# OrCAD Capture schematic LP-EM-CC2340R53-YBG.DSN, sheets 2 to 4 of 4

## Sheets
2 2_Peripherals: size A3
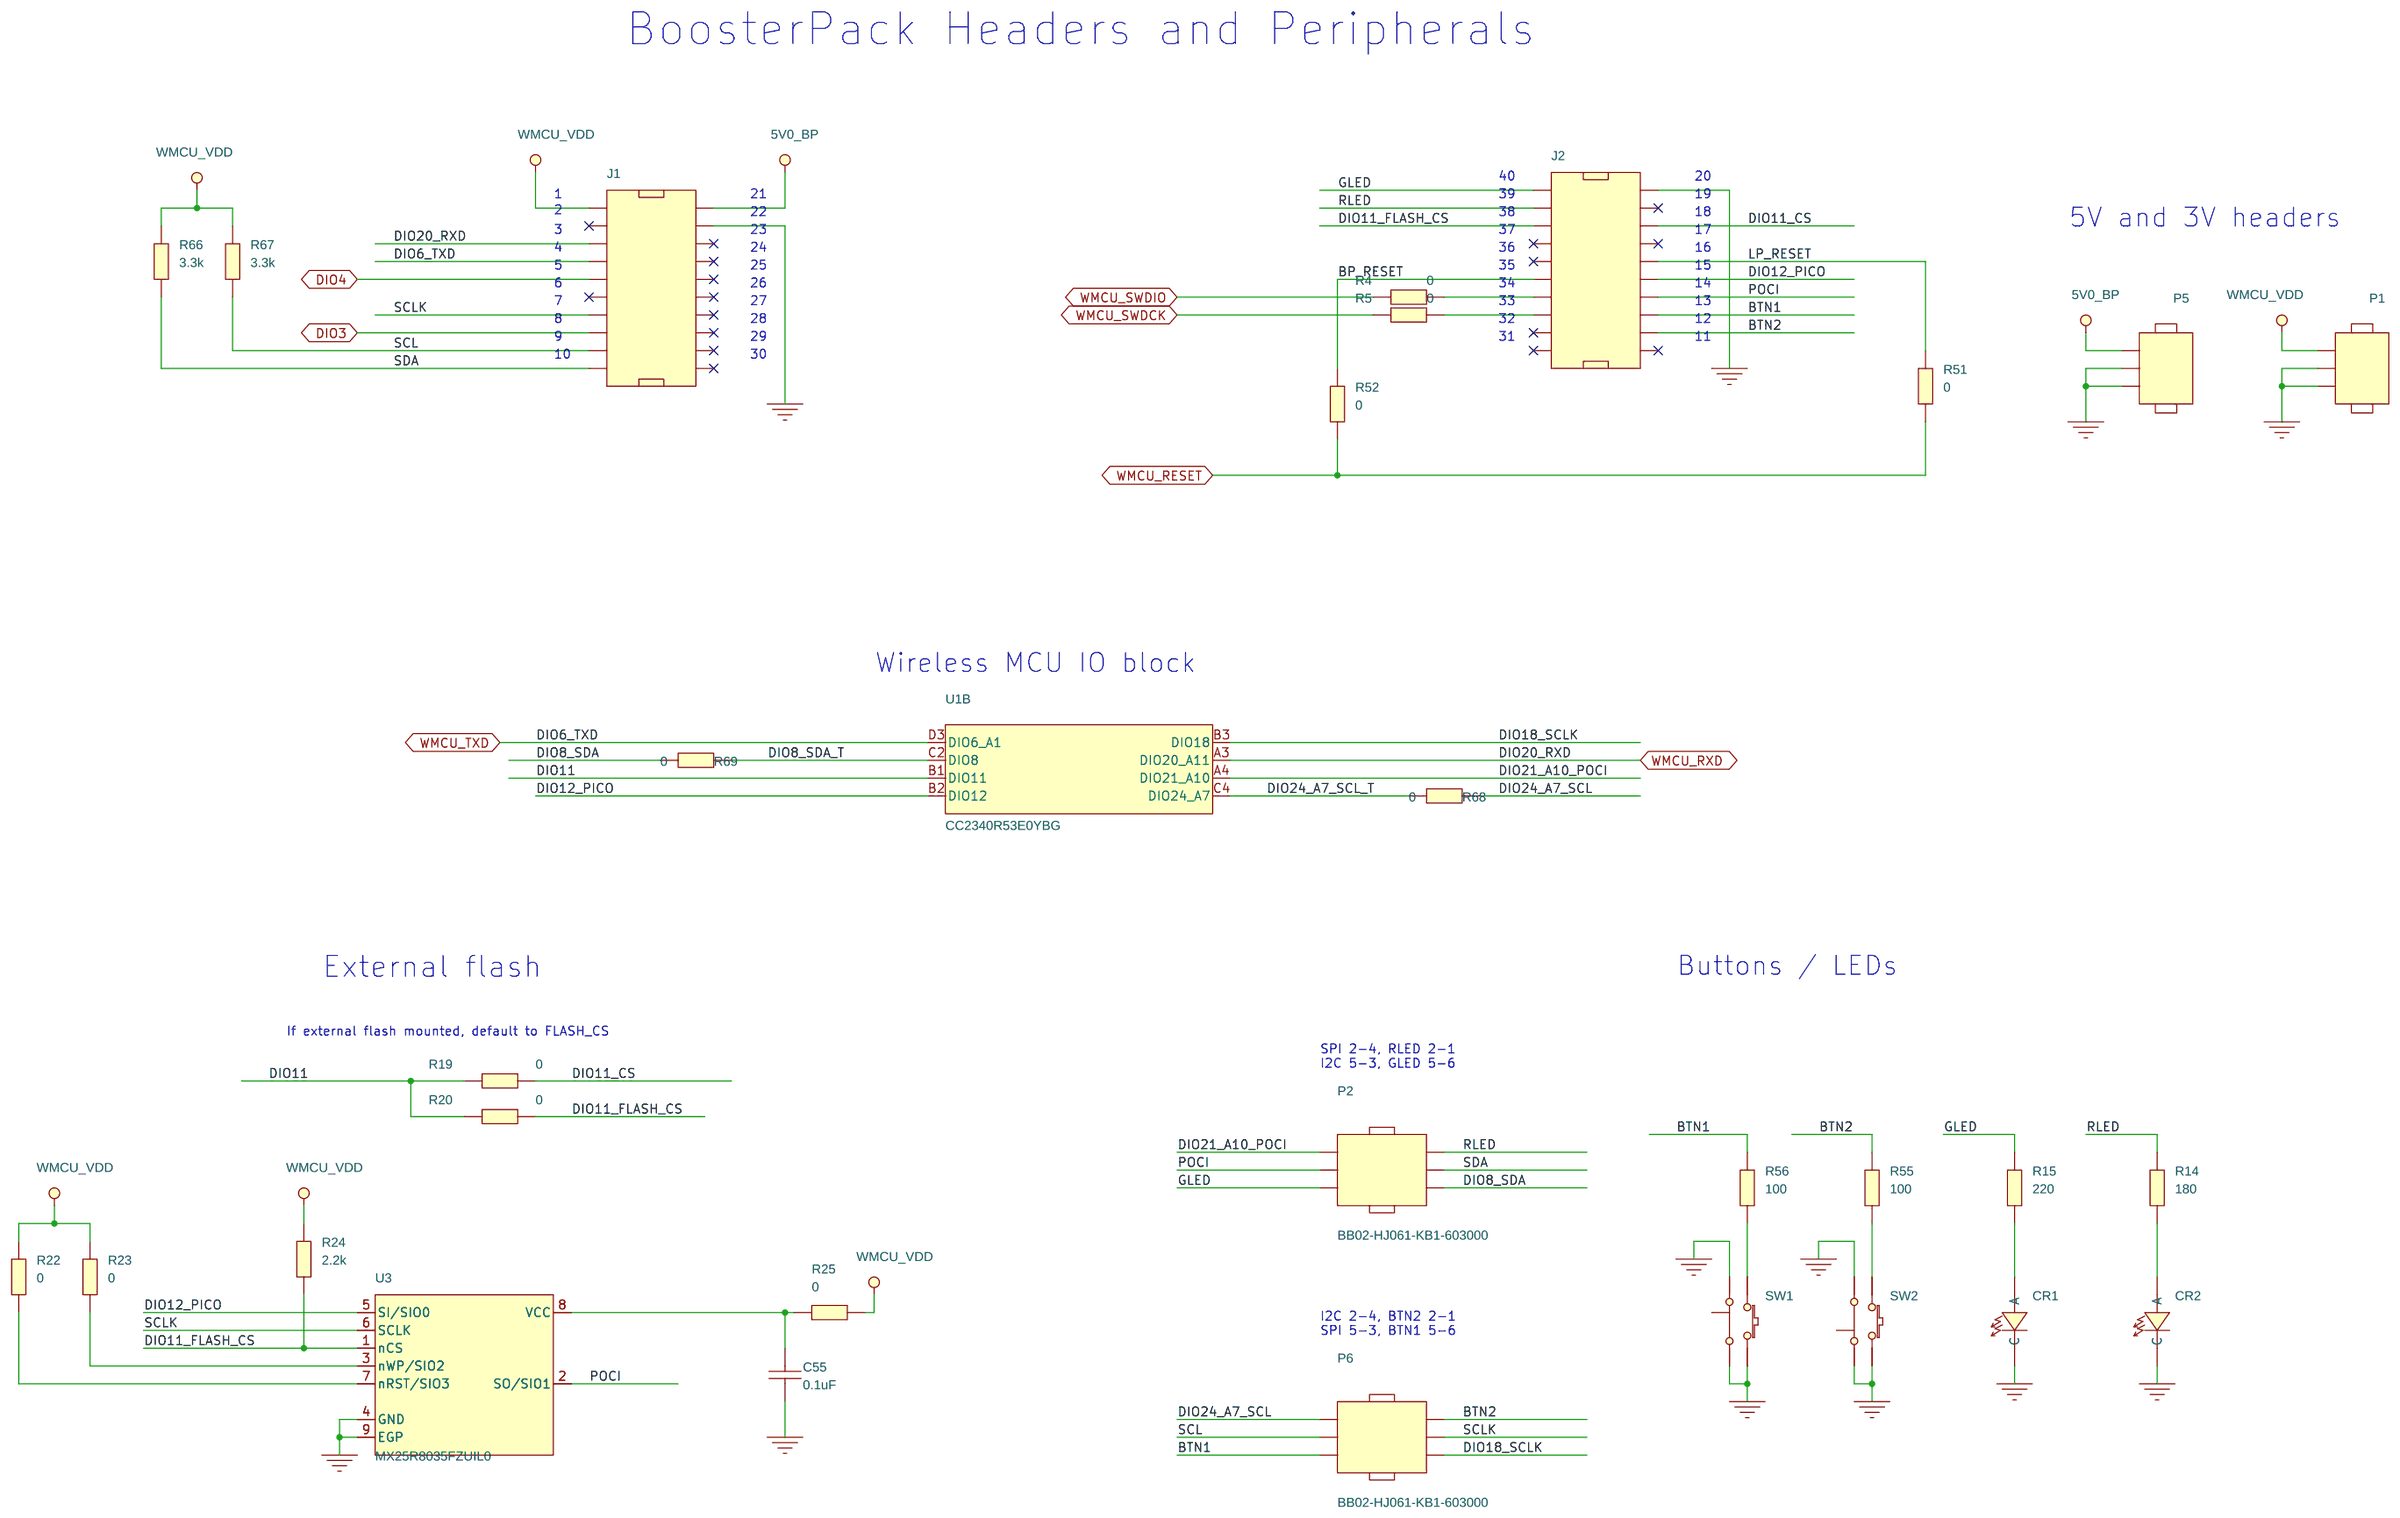
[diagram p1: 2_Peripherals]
3 3_Debugger Interface: size A3
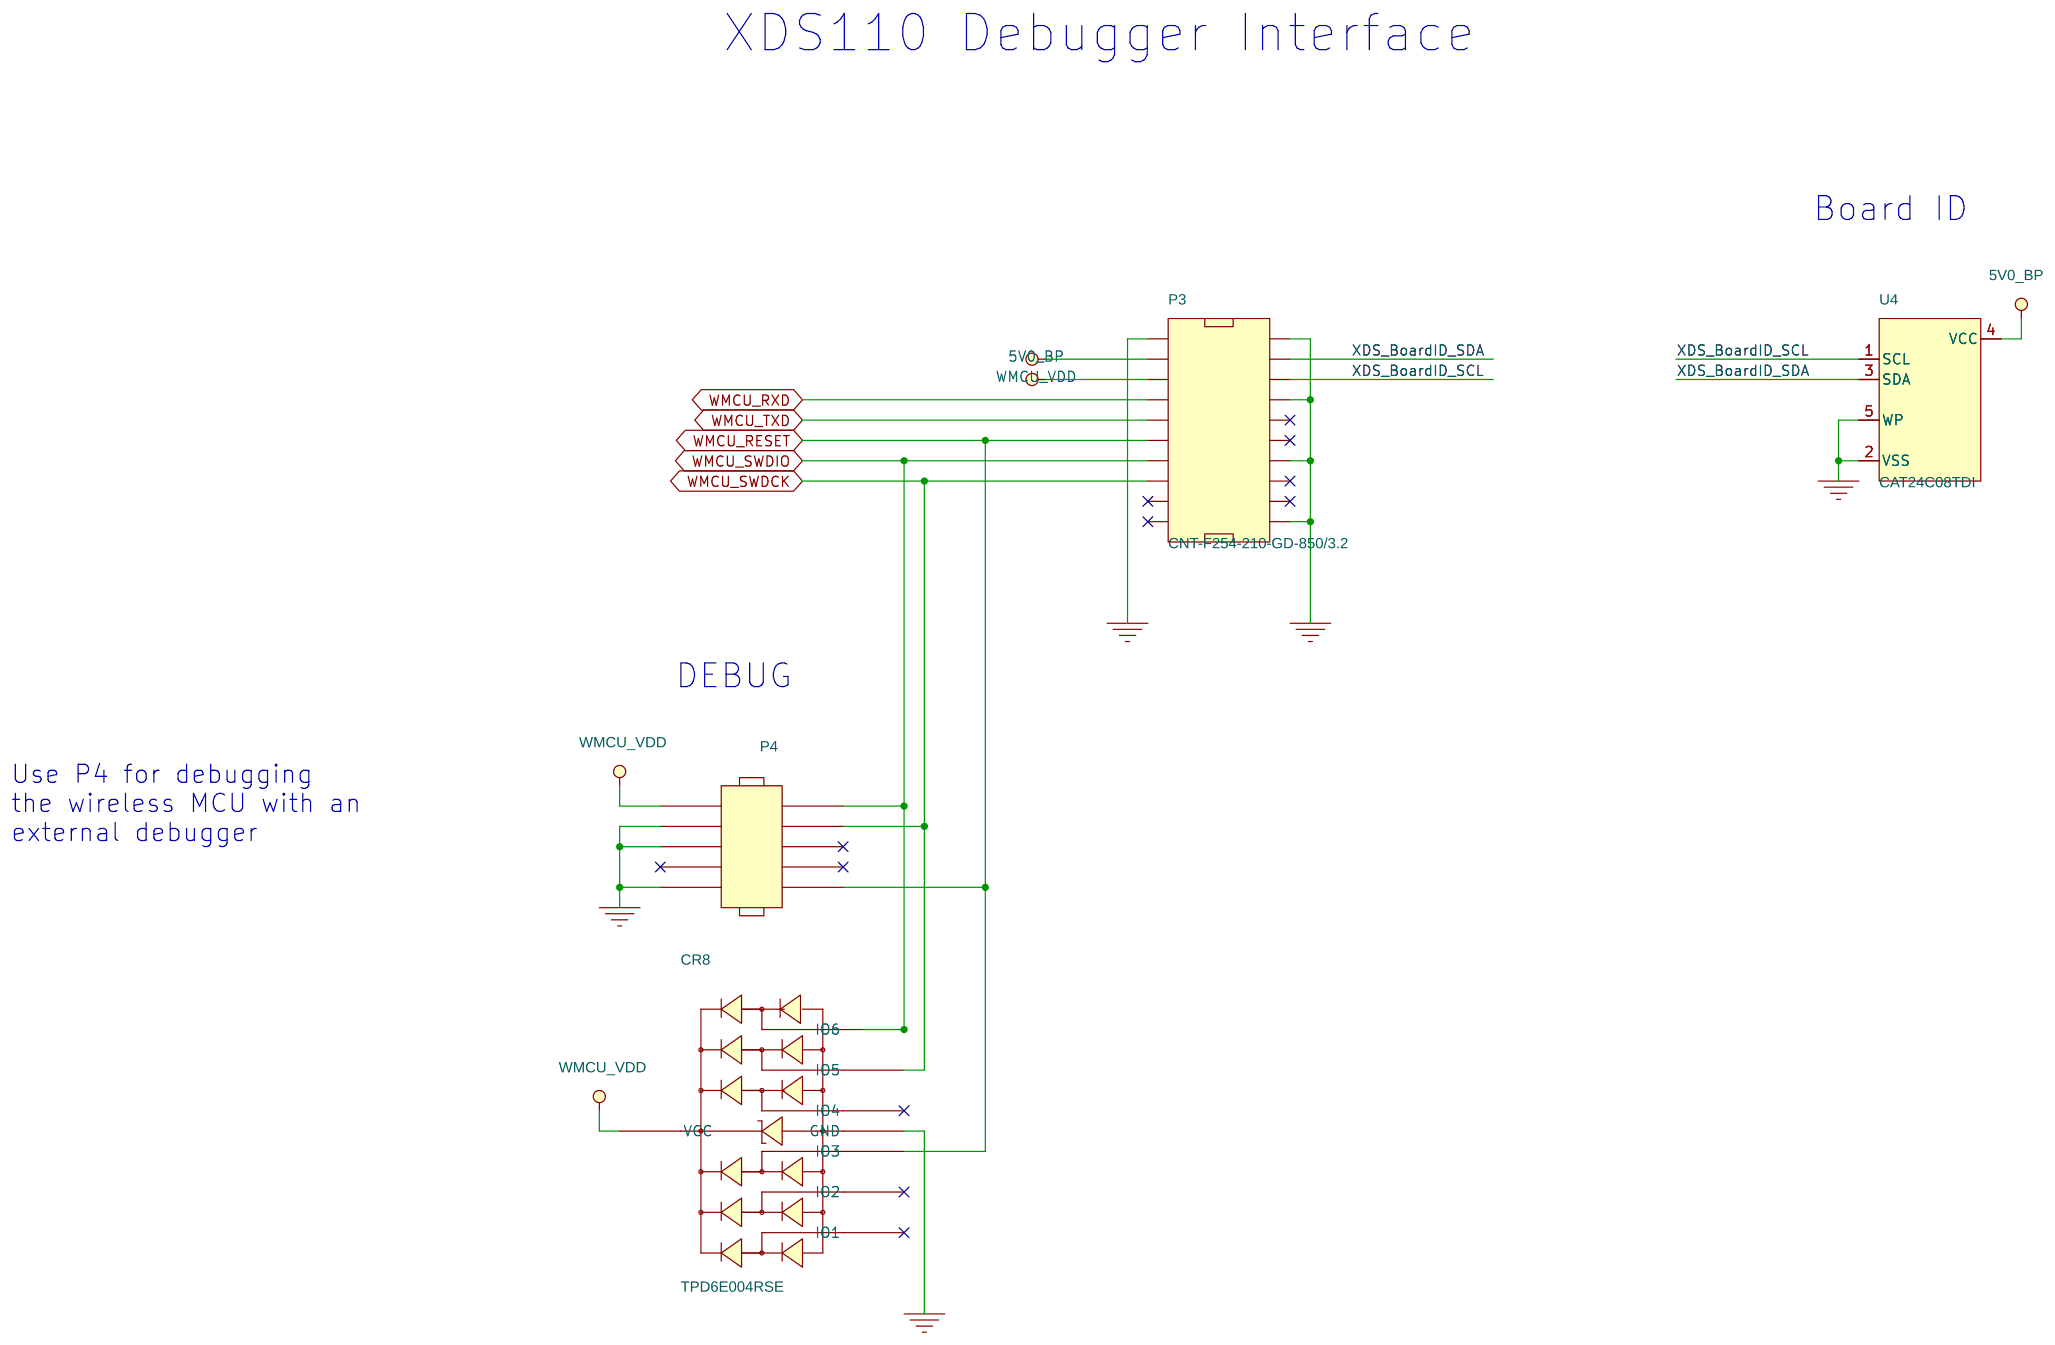
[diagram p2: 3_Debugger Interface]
4 4_Mech: size A3
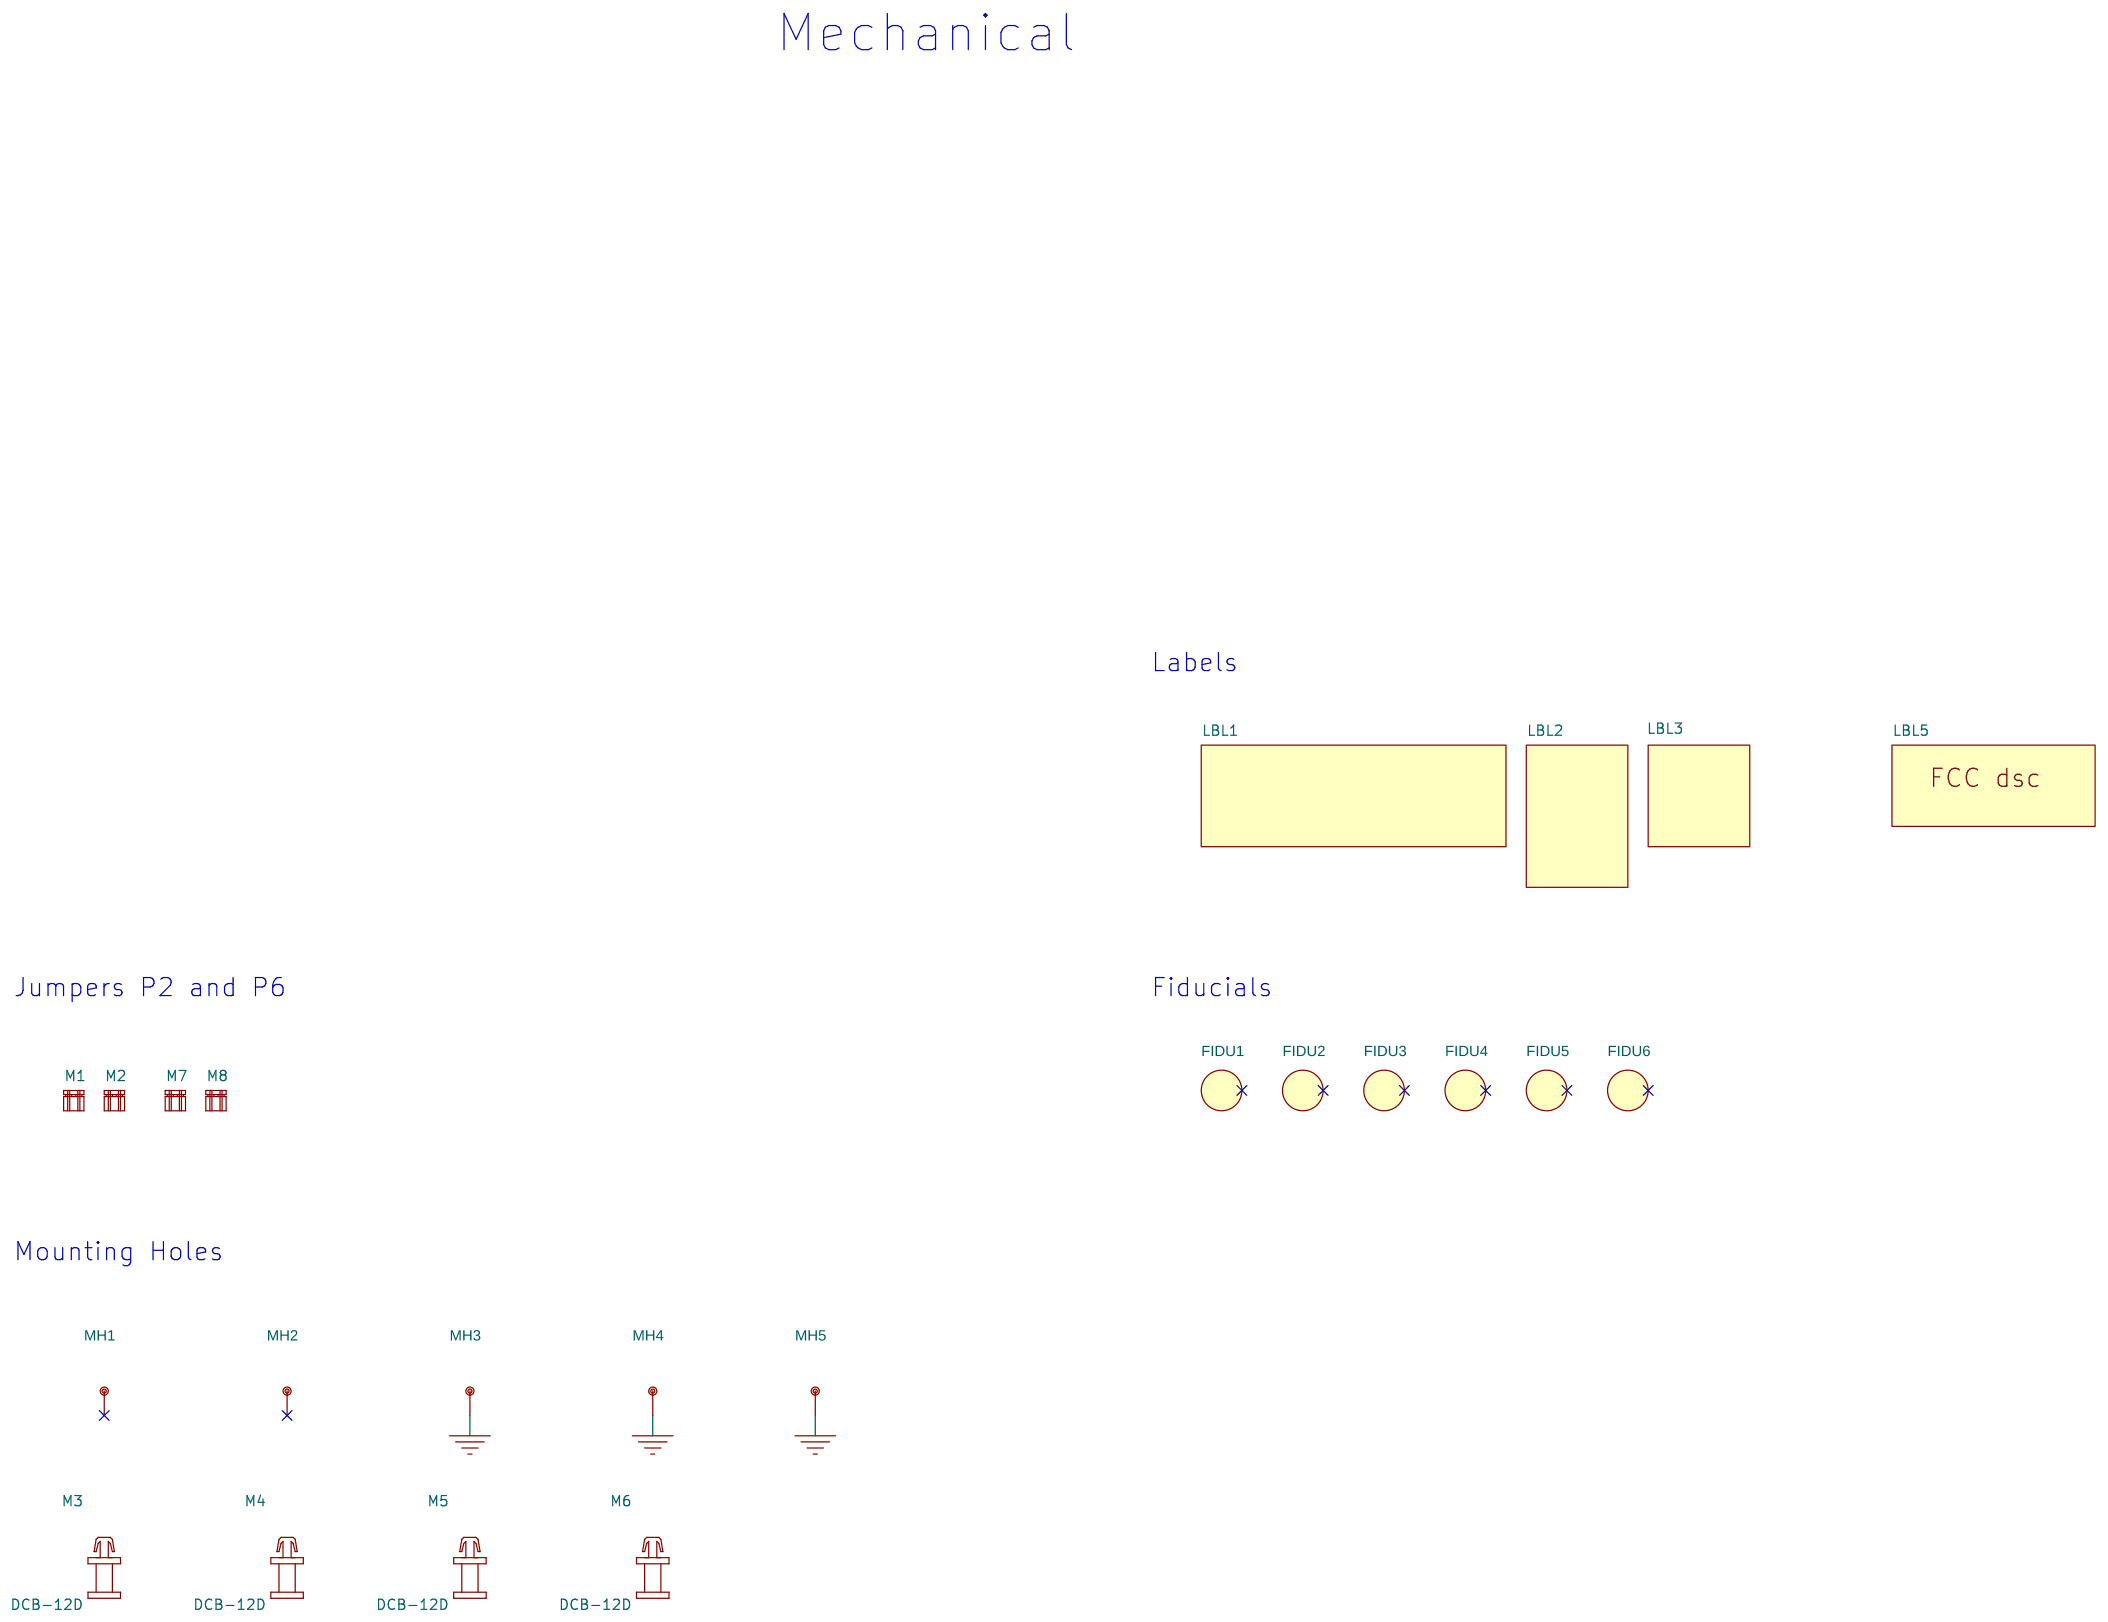
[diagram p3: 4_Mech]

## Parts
sheet 2_Peripherals
C55  0.1uF  [CAPC0603X35B2N]
CR1  LPL296-J2L2-25  [LEDC1707X65N]
CR2  LS L296-P2Q2-1  [LEDC1708X67N]
J1  SSQ-110-23-L-D  [SAMTEC_SSQ11023LD_A2B]
J2  SSQ-110-23-L-D  [SAMTEC_SSQ11023LD_A2B]
P1  BB02-HC031-KB1-603000  [GRADCONN_BB02HC031KB1603000_A2B]
P2  BB02-HJ061-KB1-603000  [GRADCONN_BB02HJ061KB1603000_A2B]
P5  BB02-HC031-KB1-603000  [GRADCONN_BB02HC031KB1603000_A2B]
P6  BB02-HJ061-KB1-603000  [GRADCONN_BB02HJ061KB1603000_A2B]
R4  0  [RESC1608X55A2N]
R5  0  [RESC1608X55A2N]
R14  180  [RESC1005X40B2N]
R15  220  [RESC1005X40B2N]
R19  0  [RESC1608X55A2N]
R20  0  [RESC1608X55A2N]
R22  0  [RESC1608X55A2N]
R23  0  [RESC1608X55A2N]
R24  2.2k  [RESC1005X40B2N]
R25  0  [RESC1608X55A2N]
R51  0  [RESC1608X55A2N]
R52  0  [RESC1608X55A2N]
R55  100  [RESC1005X40B2N]
R56  100  [RESC1005X40B2N]
R66  3.3k  [RESC1005X40B2N]
R67  3.3k  [RESC1005X40B2N]
R68  0  [RESC1005X40A2N]
R69  0  [RESC1005X40A2N]
SW1  1188E-1K2  [SW_1188E1K2V_A2N]
SW2  1188E-1K2  [SW_1188E1K2V_A2N]
U1  CC2340R53E0YBG  [BGAFC28C40P260X219X50]  (sections A,B)
U3  MX25R8035FZUIL0  [SON50P300X200X60-9B2N]
sheet 3_Debugger Interface
CR8  TPD6E004RSE  [QFNFC50P150X150X60-8A2N]
P3  CNT-F254-210-GD-850/3.2  [CNT_CNTF254210GD85032_A2B]
P4  FTSH-105-01-F-DV-K  [SAMTEC_FTSH-105-01-F-DV-K-10N]
U4  CAT24C08TDI  [SOT95P280X100-5A2N]
sheet 4_Mech
FIDU1  FIDU_1.27mm  [FID127X142]
FIDU2  FIDU_1.27mm  [FID127X142]
FIDU3  FIDU_1.27mm  [FID127X142]
FIDU4  FIDU_1.27mm  [FID127X142]
FIDU5  FIDU_1.27mm  [FID127X142]
FIDU6  FIDU_1.27mm  [FID127X142]
LBL1  TI_LOGO  [TI_LOGO_1]
LBL2  TRASH_7mm  [TRASH_7MM]
LBL3  ESD_LABEL_5x5mm  [ESD_LABEL_5X5]
LBL5  LABEL_FOR_EVALUATION_ONLY  [LABEL_FOR_EVALUATION_ONLY]
M1  SNT-100-BK-G  [SAMTEC_SNT100BKG]
M2  SNT-100-BK-G  [SAMTEC_SNT100BKG]
M3  DCB-12D  [MECH_DCB12D_A2B]
M4  DCB-12D  [MECH_DCB12D_A2B]
M5  DCB-12D  [MECH_DCB12D_A2B]
M6  DCB-12D  [MECH_DCB12D_A2B]
M7  SNT-100-BK-G  [SAMTEC_SNT100BKG]
M8  SNT-100-BK-G  [SAMTEC_SNT100BKG]
MH1  HOLE_3.2mm_PAD_3.8mm_PTH  [MTG320_380]
MH2  HOLE_3.2mm_PAD_3.8mm_PTH  [MTG320_380]
MH3  HOLE_3.2mm_PAD_3.8mm_PTH  [MTG320_380]
MH4  HOLE_3.2mm_PAD_3.8mm_PTH  [MTG320_380]
MH5  HOLE_1.1mm_PTH  [MTG110_170]

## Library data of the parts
C55 = CAPACITOR: CAPACITOR, CERAMIC X7S, 0.1uF, 10V, -10%/+10%, -55DEGC/+125DEGC, 0201, SMD; ALT_SYMBOLS: CAPC0603X35B2L,CAPC0603X35B2M; Additional Datasheet URL: https://www.murata.com/en-us/products/productdetail?partno=GRM033C71A104KE14%23; AutoDoc File: https://notefied-dynamic-precision.com/DB/Apps/Desktop/Item/Object.aspx?id=115293; BU Name: TEXAS INSTRUMENTS NORWAY; Budgetary Price: .01328 USD; Client Status: UNDER_REVIEW; Country of Origin: China, Japan, Philippines, Singapore; Datasheet URL: https://search.murata.co.jp/Ceramy/image/img/A01X/G101/ENG/GRM033C71A104KE14-01A.pdf; Datasheet URL 1: http://psearch.en.murata.com/capacitor/product/GRM155R71E104KE14%23.pdf; Datasheet URL 2: http://search.murata.co.jp/Ceramy/image/img/w_hinm/L0005E.pdf; Definied Quality: INDUSTRIAL; Dielectric Type: X7S; Esd Level: N/A; Lead Time: 23; LifeCycle Status: ACTIVE; MPN: CAPACITOR_0402_100nF_X7R_M_+/-10%_10V; MPN Status: ACTIVE; MSL: N/A; MTBF: N/A; MTBF Standard: N/A; Manufacturer: MANUFACTURER SELECTION; Mass: 0.00033g; Max Oper Temp: +125DEGC; Max Tol: +10%; Maximum Operating Temperature: +125DEGC; Maximum Tolerance: +10%; Min Oper Temp: -55DEGC; Min Tol: -10%; Minimum Operating Temperature: -55DEGC; Minimum Tolerance: -10%; Mounting Type: SMD; NOTE Status: PREFERRED; NOTEfied URL: https://dev-webinterface.dpserver.no/item/31254761; Old Footprint: CAPC1005X60N; PCB Package: 0201; Packing Size: 15000; Packing Type: Tape & Reel; Part Number: 02-10308; Part Type: Capacitor|CERAMIC|0201|STANDARD; REACH/SVHC Compliance: Compliant; REACH/SVHC Details: SVHC List Version Jan 19, 2021; REACH/SVHC Source: REACH Declaration; REACH/SVHC Status: Unaffected; REACH/SVHC_COMPLIANCE: COMPLIANT; REACH/SVHC_DETAILS: SVHC LIST VERSION Jun 20, 2016; REACH/SVHC_SOURCE: REACH DECLARATION; REACH/SVHC_STATUS: UNAFFECTED; ROHS: Compliant; Rated Voltage: 10V; Revision: R003; RoHS Status: ROHS_COMPLIANT; Rtd Voltage: 25V; Status: Released; Texas Part Status: Under Review; Type: Capacitor; Vendor: MURATA; Vendor Part Number: GRM033C71A104KE14D; Vendor Part Status: Active; WEIGHT: 0.0016g
CR1 = LED: OPTO, LED, InGaAlP, GREEN, 560nm, 1.8V TO 2.4V, 0.02A, 0603, SMD; ALT_SYMBOLS: LEDC1707X65L,LEDC1707X65M; Additional Datasheet URL: https://ams-osram.com/products/leds/color-leds/osram-smartled-0603-lp-l296; AutoDoc File: http://notefied-dynamic-precision.com/DB/Apps/Desktop/Item/Object.aspx?id=81622; Budget Currency: USD; Budget Price: 0.1263; CLASS: IC; Country of Origin: Missing Info; Datasheet URL: https://look.ams-osram.com/m/37da308c02be71bd/original/LP-L296.pdf; Datasheet URL 1: N/A; Datasheet URL 2: http://catalog.osram-os.com/jsp/download.jsp?rootPath=/media/&name=LP_L296.pdf&docPath=Graphics/00077128_0.pdf&url=/media//_en/Graphics/00077128_0.pdf; Definied Quality: INDUSTRIAL; Esd Level: HBM 2kV; FPLIST: LEDC1707X65N,LEDC1707X65L,LEDC1707X65M; MPN: LP L296-J2L2-25; MPN Status: NRND; MSL: 2; MTBF: N/A; MTBF Standard: N/A; Manufacturer: OSRAM; Mass: 0.0016g; Max Oper Temp: +100DEGC; Maximum Operating Temperature: +100DEGC; Min Oper Temp: -40DEGC; Minimum Operating Temperature: -40DEGC; Mounting Type: SMD; NOTE Status: NOT_PREFERRED; NOTEfied URL: https://dev-webinterface.dpserver.no/item/7373913; PCB Package: 0603; Packing Size: 5000; Packing Type: Tape & Reel; Part Number: 15-01023; Part Type: Opto|LED|0603; REACH/SVHC Compliance: Compliant; REACH/SVHC Details: SVHC List Version Jan 12, 2017; REACH/SVHC Source: REACH Declaration; REACH/SVHC Status: Unaffected; ROHS: Compliant; Rated Current: 0.02A; Rated Voltage: 1.8V TO 2.4V; Revision: R033; RoHS Status: ROHS_COMPLIANT; Rtd Current: 0.02A; Rtd Power: 0.08W; Rtd Voltage: 2V; Status: Released; Type: Opto; Vendor: OSRAM; Vendor Part Number: LP L296-J2L2-25; Vendor Part Status: Active; WEIGHT: 0.002g
CR2 = LED: OPTO, LED, RED, 630nm, 1.8V TO 2.3V, 0.02A, 0603, SMD; ALT_SYMBOLS: LEDC1708X67L,LEDC1708X67M; Additional Datasheet URL: https://ams-osram.com/products/leds/color-leds/osram-smartled-0603-ls-l296; AutoDoc File: http://notefied-dynamic-precision.com/DB/Apps/Desktop/Item/Object.aspx?id=88355; Budget Currency: USD; Budget Price: 0.089; CLASS: IC; Country of Origin: Missing Info; Datasheet URL: https://look.ams-osram.com/m/1ce9402ea49508df/original/LS-L296.pdf; Datasheet URL 1: http://www.osram-os.com/osram_os/en/products/product-catalog/led-light-emitting-diodes/smartled-0603/ls-l296/index.jsp?search_result=%2fosram_os%2fen%2fsearch%2fadvanced_search.jsp%3faction%3ddosearch%26inp_searchterm_1%3dLS%2bL296-P2Q2-1%26website_name%3; Datasheet URL 2: http://www.osram-os.com/Graphics/XPic5/00077119_0.pdf/LS%20L296%20-%20SMARTLED%200603.pdf; Definied Quality: INDUSTRIAL; Esd Level: HBM 2kV; FPLIST: LEDC1708X67N,LEDC1708X67L,LEDC1708X67M; MPN Status: NRND; MSL: 2; MTBF: N/A; MTBF Standard: N/A; Manufacturer: OSRAM; Mass: 0.0016g; Max Oper Temp: +100DEGC; Maximum Operating Temperature: +100DEGC; Min Oper Temp: -40DEGC; Minimum Operating Temperature: -40DEGC; Mounting Type: SMD; NOTE Status: PREFERRED; NOTEfied URL: https://dev-webinterface.dpserver.no/item/7374561; PCB Package: 0603; PPCB Recomendation: Inactive for new design [Alert:0001]; Packing Size: 5000; Packing Type: Tape & Reel; Part Number: 15-01169; Part Type: Opto|LED|0603; REACH/SVHC Compliance: Compliant; REACH/SVHC Details: SVHC List Version Jan 12, 2017; REACH/SVHC Source: REACH Declaration; REACH/SVHC Status: Unaffected; ROHS: Compliant; Rated Current: 0.02A; Rated Voltage: 1.8V TO 2.3V; Revision: R034; RoHS Status: ROHS_COMPLIANT; Rtd Current: 0.06A; Rtd Voltage: 1.8V TO 2.3V; Status: Released; Type: Opto; Vendor: OSRAM; Vendor Part Status: Active; WEIGHT: 0.002g
J1 J2 = CONN_HEADER_2X10_J_S_V1: CONNECTOR, HEADER, FEMALE, STRAIGHT, 2 ROW(S), 20 PIN(S), 2.54mm, PTH; ALT_SYMBOLS: SAMTEC_SSQ11023LD_A2A,SAMTEC_SSQ11023LD_A2C; Additional Datasheet URL: https://www.samtec.com/products/ssq-110-23-l-d; AutoDoc File: http://notefied-dynamic-precision.com/DB/Apps/Desktop/Item/Object.aspx?id=104387; Budget Currency: USD; Budget Price: 2.14; Budgetary Price: 2.62146 USD; Country of Origin: China, Costa Rica, Malaysia, Singapore, Taiwan, United States, Vietnam; Datasheet URL: https://suddendocs.samtec.com/catalog_english/ssq_th.pdf; Datasheet URL 1: http://suddendocs.samtec.com/prints/ssq-1xx-xx-xxx-x-xx-xxx-xx-x-mkt.pdf; Datasheet URL 2: http://suddendocs.samtec.com/catalog_english/ssq_th.pdf; Definied Quality: INDUSTRIAL; Esd Level: N/A; FPLIST: SAMTEC_SSQ11023LD_A2B,SAMTEC_SSQ11023LD_A2C,SAMTEC_SSQ11023LD_A2A; Lead Time: 12; LifeCycle Status: ACTIVE; MPN Status: ACTIVE; MSL: N/A; Manufacturer: SAMTEC; Mass: 2.45594g; Max Oper Temp: +125DEGC; Maximum Operating Temperature: +125DEGC; Min Oper Temp: -55DEGC; Minimum Operating Temperature: -55DEGC; Mounting Type: PTH; NOTE Status: PREFERRED; NOTEfied URL: https://dev-webinterface.dpserver.no/item/7324084; No Of Pos: 20; No Of Rows: 2; Number of Positions: 20; Number of Rows: 2; Packing Size: 21; Packing Type: Bulk; Part Number: 06-04997; Part Type: Connector|HEADER|STANDARD; Pitch: 2.54mm; REACH/SVHC Compliance: Compliant; REACH/SVHC Details: SVHC List Version Jan 12, 2017; REACH/SVHC Source: REACH Declaration; REACH/SVHC Status: Unaffected; ROHS: Compliant; Rated Current: 6.3A; Rated Voltage: 465VAC / 655VDC; Revision: R022; RoHS Status: ROHS_COMPLIANT; Rtd Current: 6.3A; Status: Released; Texas Part Status: Under Review; Type: Connector; Vendor: SAMTEC; Vendor Part Status: Active; WEIGHT: 2.45594g
P1 P5 = CONN_HEADER_3_P_S: CONNECTOR, HEADER, MALE, STRAIGHT, 1 ROW(S), 3 PIN(S), PITCH 2.54mm, PTH; ALT_SYMBOLS: GRADCONN_BB02HC031KB1603000_A2A,GRADCONN_BB02HC031KB1603000_A2C; Additional Datasheet URL: https://www.gradconn.com/Products/BoardToBoard/All/BB02-HC; AutoDoc File: http://notefied-dynamic-precision.com/DB/Apps/Desktop/Item/Object.aspx?id=104636; Country of Origin: Missing Info; Datasheet URL: https://www.gradconn.com/files/Drawings/BB02-HC.pdf; Datasheet URL 1: http://www.gradconn.com/Files/Drawings/BB02-HC.pdf; Datasheet URL 2: http://www.gradconn.com/Files/Specs/BTB-2.54mm-Header-specification.pdf; MPN Status: ACTIVE; Manufacturer: GRADCONN; Mass: N/A; Max Oper Temp: +105DEGC; Maximum Operating Temperature: +105DEGC; Min Oper Temp: -40DEGC; Minimum Operating Temperature: -40DEGC; Mounting Type: PTH; NOTE Status: PREFERRED; NOTEfied URL: https://dev-webinterface.dpserver.no/item/7324030; No Of Pos: 3; No Of Rows: 1; Number of Positions: 3; Number of Rows: 1; Packing Size: N/A; Packing Type: Missing Info; Part Number: 06-05038; Part Type: Connector|HEADER|STANDARD; Pitch: 2.54mm; REACH/SVHC Compliance: Compliant; REACH/SVHC Details: SVHC List Version Jun 20, 2016; REACH/SVHC Source: RoHS & REACH Declaration; REACH/SVHC Status: Unaffected; ROHS: Compliant; Rated Current: 3A; Rated Voltage: 250V; Revision: R023; RoHS Status: ROHS_COMPLIANT; Rtd Current: 3A; Rtd Voltage: 250V; Status: Released; Texas Part Status: Under Review; Type: Connector; Vendor: GRADCONN; Vendor Part Status: Active
P2 P6 = CONN_HEADER_2X3_P_V2: CONNECTOR, HEADER, MALE, STRAIGHT, 2 ROW(S), 6 PIN(S), PITCH 2.54mm, PTH; ALT_SYMBOLS: GRADCONN_BB02HJ061KB1603000_A2A,GRADCONN_BB02HJ061KB1603000_A2C; Additional Datasheet URL: https://www.gradconn.com/Products/BoardToBoard/All/BB02-HJ; Country of Origin: Missing Info; Datasheet URL: https://www.gradconn.com/files/Drawings/BB02-HJ.pdf; Maximum Operating Temperature: +105DEGC; Minimum Operating Temperature: -40DEGC; Mounting Type: PTH; NOTEfied URL: https://dev-webinterface.dpserver.no/item/30968420; Number of Positions: 6; Number of Rows: 2; Packing Size: N/A; Packing Type: Loose; Part Number: 06-10909; Part Type: Connector|HEADER|STANDARD; Pitch: 2.54mm; REACH/SVHC Compliance: Compliant; REACH/SVHC Details: SVHC List Version Jun 25, 2020; REACH/SVHC Source: RoHS & REACH Declaration; REACH/SVHC Status: Unaffected; ROHS: Compliant; Rated Current: 3A; Revision: R003; Status: Released; Texas Part Status: Under Review; Type: Connector; Vendor: GRADCONN; Vendor Part Status: Active
R4 R5 R19 R20 R22 R23 R25 R51 R52 = RESISTOR: RESISTOR, THICK FILM, JUMPER, 0, 0R/+0.02R, 0.1W, 2A, -55DEGC/+155DEGC, 0603, SMD; ALT_SYMBOLS: RESC1608X55A2L,RESC1608X55A2M; Additional Datasheet URL: N/A; AutoDoc File: https://notefied-dynamic-precision.com/DB/Apps/Desktop/Item/Object.aspx?id=94847; BU Name: DYNAMIC PRECISION GDANSK; Budget Currency: USD; Budget Price: 0.0016; Budgetary Price: .005 EUR; Client Status: UNDER_REVIEW; Country of Origin: Israel; Datasheet URL: http://www.vishay.com/docs/20035/dcrcwe3.pdf; Datasheet URL 1: http://www.vishay.com/docs/20035/dcrcwe3.pdf; Datasheet URL 2: N/A; Esd Level: N/A; Lead Time: 29; LifeCycle Status: ACTIVE; MPN: DNM; MPN Status: ACTIVE; MSL: N/A; MTBF: N/A; MTBF Standard: N/A; Manufacturer: DO NOT MOUNT; Mass: 0.002g; Max Oper Temp: +155DEGC; Max TC: N/A; Max Tol: +0.02R; Maximum Operating Temperature: +155DEGC; Maximum Temperature Coefficient: N/A; Maximum Tolerance: +0.02R; Min Oper Temp: -55DEGC; Min TC: N/A; Min Tol: 0R; Minimum Operating Temperature: -55DEGC; Minimum Temperature Coefficient: N/A; Minimum Temperature Coeficient: N/A; Minimum Tolerance: 0R; Mounting Type: SMD; NOTE Status: PREFERRED; NOTEfied URL: https://dev-webinterface.dpserver.no/item/7245735; Old Footprint: RESC1608X55N,0603; PCB Package: 0603; Packing Size: 20000; Packing Type: Tape & Reel; Part Number: 01-20043; Part Type: Resistor|0603|JUMPER; REACH/SVHC Compliance: Compliant; REACH/SVHC Details: SVHC List Version Jun 15, 2015; REACH/SVHC Source: Material Declaration; REACH/SVHC Status: Unaffected; REACH/SVHC_COMPLIANCE: COMPLIANT; REACH/SVHC_DETAILS: SVHC LIST VERSION Jun 15, 2015; REACH/SVHC_SOURCE: MATERIAL DECLARATION; REACH/SVHC_STATUS: UNAFFECTED; ROHS: Exempt; Rated Current: 2A; Rated Power: 0.1W; Rated Voltage: N/A; Resistor Type: THICK FILM; Revision: R010; RoHS Status: ROHS_COMPLIANT_WITH_EXEMPTION; Rtd Current: N/A; Rtd Power: 0.1W; Rtd Voltage: 75V; Status: Released; Type: Resistor; Vendor: VISHAY; Vendor Part Number: CRCW06030000Z0EC; Vendor Part Status: Active; WEIGHT: 0.002g
R14 = RESISTOR: RESISTOR, THICK FILM, 180, -5%/+5%, 0.063W, 50V, -55DEGC/+155DEGC, 0402, SMD; Additional Datasheet URL: https://www.vishay.com/en/product/20035/; AutoDoc File: https://notefied-dynamic-precision.com/DB/Apps/Desktop/Item/Object.aspx?id=113318; BU Name: TEXAS INSTRUMENTS NORWAY; Budget Currency: EUR; Budget Price: 0.014; Budgetary Price: .014 EUR; Client Status: UNDER_REVIEW; Country of Origin: China, Israel; Datasheet URL: https://www.vishay.com/docs/20035/dcrcwe3.pdf; Datasheet URL 1: http://www.vishay.com/docs/20035/dcrcwe3.pdf; Datasheet URL 2: N/A; Definied Quality: INDUSTRIAL; Esd Level: N/A; Lead Time: 18; LifeCycle Status: ACTIVE; MPN: RESISTOR_0402_180_+/-5%_50V_0.063W_M_+/-200ppm; MPN Status: ACTIVE; MSL: N/A; MTBF: N/A; MTBF Standard: N/A; Manufacturer: MANUFACTURER SELECTION; Mass: 0.00065g; Max Oper Temp: +155DEGC; Max TC: +200PPM/DEGC; Max Tol: +5%; Maximum Operating Temperature: +155DEGC; Maximum Temperature Coefficient: +200PPM/DEGC; Maximum Tolerance: +5%; Min Oper Temp: -55DEGC; Min TC: -200PPM/DEGC; Min Tol: -5%; Minimum Operating Temperature: -55DEGC; Minimum Temperature Coefficient: -200PPM/DEGC; Minimum Temperature Coeficient: -200PPM/DEGC; Minimum Tolerance: -5%; Mounting Type: SMD; NOTE Status: PREFERRED; NOTEfied URL: https://dev-webinterface.dpserver.no/item/7253041; Notes: Standard item: Duplicate Reason: custom footprint for TEXAS INSTRUMENTS NORWAY.; Old Footprint: RESC1005X40N; PCB Package: 0402; Packing Size: 10000; Packing Type: Tape & Reel; Part Number: 01-22345; Part Type: Resistor|0402|STANDARD; REACH/SVHC Compliance: Compliant; REACH/SVHC Details: SVHC List Version Jun 20, 2016; REACH/SVHC Source: Material Declaration; REACH/SVHC Status: Unaffected; REACH/SVHC_COMPLIANCE: COMPLIANT; REACH/SVHC_DETAILS: SVHC LIST VERSION Jun 20, 2016; REACH/SVHC_SOURCE: MATERIAL DECLARATION; REACH/SVHC_STATUS: UNAFFECTED; ROHS: Exempt; Rated Current: N/A; Rated Power: 0.063W; Rated Voltage: 50V; Resistor Type: THICK FILM; Revision: R024; RoHS Status: ROHS_COMPLIANT_WITH_EXEMPTION; Rtd Current: N/A; Rtd Power: 0.063W; Rtd Voltage: 50V; Status: Released; Texas Part Status: Under Review; Type: Resistor; Vendor: VISHAY; Vendor Part Number: CRCW0402180RJNED; Vendor Part Status: Active; WEIGHT: 0.00065g
R15 = RESISTOR: RESISTOR, THICK FILM, 220, -5%/+5%, 0.063W, 50V, -55DEGC/+155DEGC, 0402, SMD; Additional Datasheet URL: https://www.vishay.com/en/product/20035/; AutoDoc File: https://notefied-dynamic-precision.com/DB/Apps/Desktop/Item/Object.aspx?id=113319; BU Name: TEXAS INSTRUMENTS NORWAY; Budget Currency: EUR; Budget Price: 0.014; Budgetary Price: .014 EUR; Client Status: UNDER_REVIEW; Country of Origin: China, Israel; Datasheet URL: https://www.vishay.com/docs/20035/dcrcwe3.pdf; Datasheet URL 1: http://www.vishay.com/docs/20035/dcrcwe3.pdf; Datasheet URL 2: N/A; Definied Quality: INDUSTRIAL; Esd Level: N/A; Lead Time: 18; LifeCycle Status: ACTIVE; MPN: RESISTOR_0402_220_+/-5%_50V_0.063W_M_+/-200ppm; MPN Status: ACTIVE; MSL: N/A; MTBF: N/A; MTBF Standard: N/A; Manufacturer: MANUFACTURER SELECTION; Mass: 0.00065g; Max Oper Temp: +155DEGC; Max TC: +200PPM/DEGC; Max Tol: +5%; Maximum Operating Temperature: +155DEGC; Maximum Temperature Coefficient: +200PPM/DEGC; Maximum Tolerance: +5%; Min Oper Temp: -55DEGC; Min TC: -200PPM/DEGC; Min Tol: -5%; Minimum Operating Temperature: -55DEGC; Minimum Temperature Coefficient: -200PPM/DEGC; Minimum Temperature Coeficient: -200PPM/DEGC; Minimum Tolerance: -5%; Mounting Type: SMD; NOTE Status: PREFERRED; NOTEfied URL: https://dev-webinterface.dpserver.no/item/7253039; Notes: Standard item: Duplicate Reason: custom footprint for TEXAS INSTRUMENTS NORWAY.; Old Footprint: RESC1005X40N; PCB Package: 0402; Packing Size: 10000; Packing Type: Tape & Reel; Part Number: 01-22346; Part Type: Resistor|0402|STANDARD; REACH/SVHC Compliance: Compliant; REACH/SVHC Details: SVHC List Version Jun 20, 2016; REACH/SVHC Source: Material Declaration; REACH/SVHC Status: Unaffected; REACH/SVHC_COMPLIANCE: COMPLIANT; REACH/SVHC_DETAILS: SVHC LIST VERSION Jun 20, 2016; REACH/SVHC_SOURCE: MATERIAL DECLARATION; REACH/SVHC_STATUS: UNAFFECTED; ROHS: Exempt; Rated Current: N/A; Rated Power: 0.063W; Rated Voltage: 50V; Resistor Type: THICK FILM; Revision: R024; RoHS Status: ROHS_COMPLIANT_WITH_EXEMPTION; Rtd Current: N/A; Rtd Power: 0.063W; Rtd Voltage: 50V; Status: Released; Texas Part Status: Under Review; Type: Resistor; Vendor: VISHAY; Vendor Part Number: CRCW0402220RJNED; Vendor Part Status: Active; WEIGHT: 0.00065g
R24 = RESISTOR: RESISTOR, THICK FILM, 2.2k, -5%/+5%, 0.063W, 50V, -55DEGC/+155DEGC, 0402, SMD; Additional Datasheet URL: https://www.vishay.com/en/product/20035/; AutoDoc File: https://notefied-dynamic-precision.com/DB/Apps/Desktop/Item/Object.aspx?id=114560; BU Name: TEXAS INSTRUMENTS NORWAY; Budget Currency: EUR; Budget Price: 0.014; Budgetary Price: .014 EUR; Client Status: UNDER_REVIEW; Country of Origin: China, Israel; Datasheet URL: https://www.vishay.com/docs/20035/dcrcwe3.pdf; Datasheet URL 1: http://www.vishay.com/docs/20035/dcrcwe3.pdf; Datasheet URL 2: N/A; Definied Quality: INDUSTRIAL; Esd Level: N/A; Lead Time: 18; LifeCycle Status: ACTIVE; MPN: RESISTOR_0402_2.2k_+/-5%_50V_0.063W_M_+/-200ppm; MPN Status: ACTIVE; MSL: N/A; MTBF: N/A; MTBF Standard: N/A; Manufacturer: MANUFACTURER SELECTION; Mass: 0.00065g; Max Oper Temp: +155DEGC; Max TC: +200PPM/DEGC; Max Tol: +5%; Maximum Operating Temperature: +155DEGC; Maximum Temperature Coefficient: +200PPM/DEGC; Maximum Tolerance: +5%; Min Oper Temp: -55DEGC; Min TC: -200PPM/DEGC; Min Tol: -5%; Minimum Operating Temperature: -55DEGC; Minimum Temperature Coefficient: -200PPM/DEGC; Minimum Temperature Coeficient: -200PPM/DEGC; Minimum Tolerance: -5%; Mounting Type: SMD; NOTE Status: PREFERRED; NOTEfied URL: https://dev-webinterface.dpserver.no/item/7253343; Notes: Standard item: Duplicate Reason: custom footprint for TEXAS INSTRUMENTS NORWAY.; Old Footprint: RESC1005X40N; PCB Package: 0402; Packing Size: 10000; Packing Type: Tape & Reel; Part Number: 01-22487; Part Type: Resistor|0402|STANDARD; REACH/SVHC Compliance: Compliant; REACH/SVHC Details: SVHC List Version Jun 20, 2016; REACH/SVHC Source: Material Declaration; REACH/SVHC Status: Unaffected; REACH/SVHC_COMPLIANCE: COMPLIANT; REACH/SVHC_DETAILS: SVHC LIST VERSION Jun 20, 2016; REACH/SVHC_SOURCE: MATERIAL DECLARATION; REACH/SVHC_STATUS: UNAFFECTED; ROHS: Exempt; Rated Current: N/A; Rated Power: 0.063W; Rated Voltage: 50V; Resistor Type: THICK FILM; Revision: R024; RoHS Status: ROHS_COMPLIANT; Rtd Current: N/A; Rtd Power: 0.063W; Rtd Voltage: 50V; Status: Released; Texas Part Status: Under Review; Type: Resistor; Vendor: VISHAY; Vendor Part Number: CRCW04022K20JNED; Vendor Part Status: Active; WEIGHT: 0.00065g
R55 R56 = RESISTOR: RESISTOR, THICK FILM, 100, -5%/+5%, 0.063W, 50V, -55DEGC/+155DEGC, 0402, SMD; Additional Datasheet URL: https://www.vishay.com/en/product/20035/; AutoDoc File: https://notefied-dynamic-precision.com/DB/Apps/Desktop/Item/Object.aspx?id=114555; BU Name: TEXAS INSTRUMENTS NORWAY; Budget Currency: USD; Budget Price: 0.0014; Budgetary Price: .0014 USD; Client Status: UNDER_REVIEW; Country of Origin: China, Israel; Datasheet URL: https://www.vishay.com/docs/20035/dcrcwe3.pdf; Datasheet URL 1: http://www.vishay.com/docs/20035/dcrcwe3.pdf; Datasheet URL 2: N/A; Definied Quality: INDUSTRIAL; Esd Level: N/A; Lead Time: 16; LifeCycle Status: ACTIVE; MPN: RESISTOR_0402_100_+/-5%_50V_0.063W_M_+/-200ppm; MPN Status: ACTIVE; MSL: N/A; MTBF: N/A; MTBF Standard: N/A; Manufacturer: MANUFACTURER SELECTION; Mass: 0.00065g; Max Oper Temp: +155DEGC; Max TC: +200PPM/DEGC; Max Tol: +5%; Maximum Operating Temperature: +155DEGC; Maximum Temperature Coefficient: +200PPM/DEGC; Maximum Tolerance: +5%; Min Oper Temp: -55DEGC; Min TC: -200PPM/DEGC; Min Tol: -5%; Minimum Operating Temperature: -55DEGC; Minimum Temperature Coefficient: -200PPM/DEGC; Minimum Temperature Coeficient: -200PPM/DEGC; Minimum Tolerance: -5%; Mounting Type: SMD; NOTE Status: PREFERRED; NOTEfied URL: https://dev-webinterface.dpserver.no/item/7253339; Notes: Standard item: Duplicate Reason: custom footprint for TEXAS INSTRUMENTS NORWAY.; Old Footprint: RESC1005X40N; PCB Package: 0402; Packing Size: 10000; Packing Type: Tape & Reel; Part Number: 01-22482; Part Type: Resistor|0402|STANDARD; REACH/SVHC Compliance: Compliant; REACH/SVHC Details: SVHC List Version Jun 20, 2016; REACH/SVHC Source: Material Declaration; REACH/SVHC Status: Unaffected; REACH/SVHC_COMPLIANCE: COMPLIANT; REACH/SVHC_DETAILS: SVHC LIST VERSION Jun 20, 2016; REACH/SVHC_SOURCE: MATERIAL DECLARATION; REACH/SVHC_STATUS: UNAFFECTED; ROHS: Exempt; Rated Current: N/A; Rated Power: 0.063W; Rated Voltage: 50V; Resistor Type: THICK FILM; Revision: R027; RoHS Status: ROHS_COMPLIANT; Rtd Current: N/A; Rtd Power: 0.063W; Rtd Voltage: 50V; Status: Released; Texas Part Status: Under Review; Type: Resistor; Vendor: VISHAY; Vendor Part Number: CRCW0402100RJNED; Vendor Part Status: Active; WEIGHT: 0.00065g
R66 R67 = RESISTOR: RESISTOR, THICK FILM, 3.3k, -5%/+5%, 0.063W, 50V, -55DEGC/+155DEGC, 0402, SMD; Additional Datasheet URL: https://www.vishay.com/en/product/20035/; AutoDoc File: https://notefied-dynamic-precision.com/DB/Apps/Desktop/Item/Object.aspx?id=114561; BU Name: TEXAS INSTRUMENTS NORWAY; Budget Currency: EUR; Budget Price: 0.014; Budgetary Price: .014 EUR; Client Status: UNDER_REVIEW; Country of Origin: China, Israel; Datasheet URL: https://www.vishay.com/docs/20035/dcrcwe3.pdf; Datasheet URL 1: http://www.vishay.com/docs/20035/dcrcwe3.pdf; Datasheet URL 2: N/A; Definied Quality: INDUSTRIAL; Esd Level: N/A; Lead Time: 18; LifeCycle Status: ACTIVE; MPN: RESISTOR_0402_3.3k_+/-5%_50V_0.063W_M_+/-200ppm; MPN Status: ACTIVE; MSL: N/A; MTBF: N/A; MTBF Standard: N/A; Manufacturer: MANUFACTURER SELECTION; Mass: 0.00065g; Max Oper Temp: +155DEGC; Max TC: +200PPM/DEGC; Max Tol: +5%; Maximum Operating Temperature: +155DEGC; Maximum Temperature Coefficient: +200PPM/DEGC; Maximum Tolerance: +5%; Min Oper Temp: -55DEGC; Min TC: -200PPM/DEGC; Min Tol: -5%; Minimum Operating Temperature: -55DEGC; Minimum Temperature Coefficient: -200PPM/DEGC; Minimum Temperature Coeficient: -200PPM/DEGC; Minimum Tolerance: -5%; Mounting Type: SMD; NOTE Status: PREFERRED; NOTEfied URL: https://dev-webinterface.dpserver.no/item/7253348; Notes: Standard item: Duplicate Reason: custom footprint for TEXAS INSTRUMENTS NORWAY.; Old Footprint: RESC1005X40N; PCB Package: 0402; Packing Size: 10000; Packing Type: Tape & Reel; Part Number: 01-22488; Part Type: Resistor|0402|STANDARD; REACH/SVHC Compliance: Compliant; REACH/SVHC Details: SVHC List Version Jun 20, 2016; REACH/SVHC Source: Material Declaration; REACH/SVHC Status: Unaffected; REACH/SVHC_COMPLIANCE: COMPLIANT; REACH/SVHC_DETAILS: SVHC LIST VERSION Jun 20, 2016; REACH/SVHC_SOURCE: MATERIAL DECLARATION; REACH/SVHC_STATUS: UNAFFECTED; ROHS: Exempt; Rated Current: N/A; Rated Power: 0.063W; Rated Voltage: 50V; Resistor Type: THICK FILM; Revision: R024; RoHS Status: ROHS_COMPLIANT; Rtd Current: N/A; Rtd Power: 0.063W; Rtd Voltage: 50V; Status: Released; Texas Part Status: Under Review; Type: Resistor; Vendor: VISHAY; Vendor Part Number: CRCW04023K30JNED; Vendor Part Status: Active; WEIGHT: 0.00065g
R68 R69 = RESISTOR: RESISTOR, THICK FILM, JUMPER, 0, 0R/+0.05R, 0.1W, 1A, -55DEGC/+155DEGC, 0402, SMD; ALT_SYMBOLS: RESC1005X40A2L,RESC1005X40A2M; Additional Datasheet URL: https://industrial.panasonic.com/ww/products/pt/general-purpose-chip-resistors/models/ERJ2GE0R00X; Budgetary Price: .006 EUR; Country of Origin: China, Japan, Taiwan, Thailand; Datasheet URL: https://industrial.panasonic.com/cdbs/www-data/pdf/RDA0000/AOA0000C301.pdf; Lead Time: 20; Mass: 0.00063232g; Maximum Operating Temperature: +155DEGC; Maximum Temperature Coefficient: N/A; Maximum Tolerance: +0.05R; Minimum Operating Temperature: -55DEGC; Minimum Temperature Coefficient: N/A; Minimum Temperature Coeficient: N/A; Minimum Tolerance: 0R; Mounting Type: SMD; NOTEfied URL: https://dev-webinterface.dpserver.no/item/7218612; PCB Package: 0402; Packing Size: 10000; Packing Type: Tape & Reel; Part Number: 01-11470; Part Type: Resistor|0402|JUMPER; ROHS: Exempt; Rated Current: 1A; Rated Power: 0.1W; Rated Voltage: N/A; Resistor Type: THICK FILM; Revision: R056; Status: Released; Type: Resistor; Vendor: PANASONIC INDUSTRIAL; Vendor Part Number: ERJ2GE0R00X; Vendor Part Status: Active
SW1 SW2 = SWITCH_TACT_V2: SWITCH, TACTILE, 0.05A@12VDC, 0.05A@250VAC, SMD; ALT_SYMBOLS: SW_1188E1K2V_A2L,SW_1188E1K2V_A2M; Additional Datasheet URL: http://www.dip.com.tw/en/en-product-information/en-switch004/item/2445-1188; AutoDoc File: http://notefied-dynamic-precision.com/DB/Apps/Desktop/Item/Object.aspx?id=104642; Budgetary Price: .474 EUR; CLASS: IC; Country of Origin: China; Datasheet URL: http://www.dip.com.tw/en/en-product-information/en-switch004/item/download/2483_bfc264bcfe9982a2b01570916dd931c3; Datasheet URL 1: N/A; Datasheet URL 2: http://www.dip.com.tw/en/en-product-information/en-switch004; FPLIST: SW_1188E1K2V_A2N,SW_1188E1K2V_A2L,SW_1188E1K2V_A2M; Lead Time: 18; MPN: 1188E-1K2-V-TR; MPN Status: ACTIVE; Manufacturer: DIPTRONICS; Mass: N/A; Max Oper Temp: +70DEGC; Maximum Operating Temperature: +70DEGC; Min Oper Temp: -25DEGC; Minimum Operating Temperature: -25DEGC; Mounting Type: SMD; NOTE Status: PREFERRED; NOTEfied URL: https://dev-webinterface.dpserver.no/item/7329711; Packing Size: 1500; Packing Type: Tape & Reel; Part Number: 08-00293; Part Type: Switch|TACTILE; REACH/SVHC Compliance: Compliant; REACH/SVHC Details: SVHC List Version Dec 17, 2015; REACH/SVHC Source: REACH Declaration; REACH/SVHC Status: Unaffected; ROHS: Compliant; Rated Current: 0.05A; Rated Voltage: 12VDC; Revision: R021; RoHS Status: ROHS_COMPLIANT; Rtd Current: 0.05A; Rtd Voltage: 12V; Status: Released; Texas Part Status: Under Review; Type: Switch; Vendor: DIPTRONICS; Vendor Part Number: 1188E-1K2-V-TR; Vendor Part Status: Active
U1 = IC_CC2340R5_DSBGA28_V1: IC, MICROCONTROLLER, CC2340R5, 32-bit, SIMPLELINK WIRELESS MCU ARM CORTEX -M0+, 512kbyte FLASH, 36kbyte SRAM, 12kbyte ROM, 1.71V TO 3.8V, DSBGA28, SMD; Additional Datasheet URL: https://www.ti.com/product/CC2340R5; Country of Origin: Missing Info; Datasheet URL: https://www.ti.com/lit/ds/symlink/cc2340r5.pdf; Frequency: 48MHz; Mass: N/A; Maximum Operating Temperature: +125DEGC; Minimum Operating Temperature: -40DEGC; Mounting Type: SMD; NOTEfied URL: https://dev-webinterface.dpserver.no/item/56099855; Notes: Pre-production version of CC2340R5 packaged in DSBGA28, not available publicly.; PCB Package: DSBGA28; Packing Size: N/A; Packing Type: Missing Info; Part Number: 18-38943; Part Type: IC|MICROCONTROLLER|TEXAS INSTRUMENTS; ROHS: Missing Info; Rated Voltage: 1.71V TO 3.8V; Status: Released; Texas Part Status: Under Review; Type: IC; Vendor: TEXAS INSTRUMENTS; Vendor Part Status: Preliminary
U3 = IC_FLASH_MX25R8035F_USON8: IC, MEMORY, FLASH, OTHER, 8Mbit, 8M X 1bit / 4M X 2bit / 2M X 4bit, 12ns, 1.65V TO 3.6V, uSON8, SMD; ALT_SYMBOLS: SON50P300X200X60-9B2L,SON50P300X200X60-9B2M; Additional Datasheet URL: https://www.macronix.com/en-us/products/NOR-Flash/Serial-NOR-Flash/Pages/spec.aspx?p=MX25R8035F&m=Serial%20NOR%20Flash&n=PM2164; AutoDoc File: http://notefied-dynamic-precision.com/DB/Apps/Desktop/Item/Object.aspx?id=104624; Budgetary Price: .42218 USD; Country of Origin: Taiwan; Datasheet URL: https://www.macronix.com/Lists/Datasheet/Attachments/8749/MX25R8035F,%20Wide%20Range,%208Mb,%20v1.6.pdf; Datasheet URL 1: N/A; Datasheet URL 2: http://www.macronix.com/Lists/DataSheet/Attachments/2570/MX25R8035F,%20Wide%20Range,%208Mb,%20v0.04.pdf; FPLIST: SON50P300X200X60-9B2N,SON50P300X200X60-9B2L,SON50P300X200X60-9B2M; Lead Time: 10; MPN Status: ACTIVE; Manufacturer: MACRONIX; Mass: N/A; Max Oper Temp: +85DEGC; Maximum Operating Temperature: +85DEGC; Min Oper Temp: -40DEGC; Minimum Operating Temperature: -40DEGC; Mounting Type: SMD; NOTE Status: PREFERRED; NOTEfied URL: https://dev-webinterface.dpserver.no/item/7497073; PCB Package: uSON8; Packing Size: 100; Packing Type: Tube; Part Number: 18-31726; Part Type: IC|MEMORY|FLASH|OTHER; REACH/SVHC Compliance: Compliant; REACH/SVHC Details: N/A; REACH/SVHC Source: REACH Declaration & Material Declaration; REACH/SVHC Status: Unaffected; ROHS: Compliant; Rated Voltage: 1.65V TO 3.6V; Revision: R023; RoHS Status: ROHS_COMPLIANT; Rtd Voltage: 1.65V TO 3.6V; Status: Released; Texas Part Status: Under Review; Type: IC; Vendor: MACRONIX; Vendor Part Status: Active
CR8 = DIODE_TVS_TPD6E004_QFN8_V1: DIODE, PROTECTION, ESD ARRAY - 6 CHANNELS, VCC:0.9V TO 5.5V, VBR:7V, -40DEGC/+85DEGC, QFN8, SMD; ALT_SYMBOLS: QFNFC50P150X150X60-8A2L,QFNFC50P150X150X60-8A2M; Additional Datasheet URL: https://www.ti.com/product/TPD6E004; AutoDoc File: https://notefied-dynamic-precision.com/DB/Apps/Desktop/Item/Object.aspx?id=74721; BU Name: DYNAMIC PRECISION GDANSK; Budget Currency: USD; Budget Price: 0.27; Budgetary Price: .16 USD; CLASS: IC; Client Status: UNDER_REVIEW; Country of Origin: China; Datasheet URL: https://www.ti.com/lit/gpn/TPD6E004; Datasheet URL 1: http://www.ti.com/lit/ds/symlink/tpd6e004.pdf; Datasheet URL 2: http://www.ti.com/litv/pdf/mpqf207b; FPLIST: QFN50P150X150X60-8N,QFN50P150X150X60-8AN; Lead Time: 12; Mass: 0.002839255g; Max Oper Temp: +85DEGC; Maximum Operating Temperature: +85DEGC; Min Oper Temp: -40DEGC; Minimum Operating Temperature: -40DEGC; Mounting Type: SMD; NOTEfied URL: https://dev-webinterface.dpserver.no/item/7366948; PCB Package: QFN8; Packing Size: 3000; Packing Type: Tape & Reel; Part Number: 14-05493; Part Type: Diode|PROTECTION; REACH/SVHC Compliance: Compliant; REACH/SVHC Details: SVHC List Version Jun 20, 2016; REACH/SVHC Source: Material Declaration; REACH/SVHC Status: Unaffected; ROHS: Compliant; Rated Power: N/A; Rated Voltage: 7V; Revision: R029; RoHS Status: ROHS_COMPLIANT; Rtd Power: N/A; Rtd Voltage: 7V; Status: Released; Texas Part Status: Under Review; Type: Diode; Vendor: TEXAS INSTRUMENTS; Vendor Part Number: TPD6E004RSER; Vendor Part Status: Active; Weight: 0.0033g
P3 = CONN_HEADER_2X10_J_S_V1: CONNECTOR, HEADER, FEMALE, RIGHT ANGLE, 2 ROW(S), 20 PIN(S), PITCH 2.54mm, PTH; ALT_SYMBOLS: CNT_CNTF254210GD85032_A2A,CNT_CNTF254210GD85032_A2C; Additional Datasheet URL: http://yccnt.com/cpzx/info_56.aspx?itemid=1264&lcid=28&cid=29; Country of Origin: Missing Info; Datasheet URL: http://yccnt.com/uploadfiles/2017/08/201708261737473747.pdf; Maximum Operating Temperature: +105DEGC; Minimum Operating Temperature: -40DEGC; Mounting Type: PTH; NOTEfied URL: https://dev-webinterface.dpserver.no/item/24885457; Number of Positions: 20; Number of Rows: 2; Packing Size: N/A; Packing Type: Missing Info; Part Number: 06-08434; Part Type: Connector|HEADER|STANDARD; Pitch: 2.54mm; REACH/SVHC Compliance: Missing Info; REACH/SVHC Details: N/A; REACH/SVHC Source: N/A; REACH/SVHC Status: Missing Info; ROHS: Compliant; Rated Current: 3A; Rated Voltage: 500V; Revision: R005; Status: Released; Texas Part Status: Under Review; Type: Connector; Vendor: CNT CONNECTORS; Vendor Part Status: Active
P4 = CONN_HEADER_2X5: CONNECTOR, HEADER, MALE, STRAIGHT, 2 ROW(S), 10 PIN(S), PITCH 1.27mm, SMD; ALT_SYMBOLS: SAMTEC_FTSH10501FDVK_A2L,SAMTEC_FTSH10501FDVK_A2M,SAMTEC_FTSH10501FDVK_B2L,SAMTEC_FTSH10501FDVK_B2M; Additional Datasheet URL: https://www.samtec.com/products/ftsh-105-01-f-dv-k; AutoDoc File: http://notefied-dynamic-precision.com/DB/Apps/Desktop/Item/Object.aspx?id=50836; Budget Currency: USD; Budget Price: 1.700; Budgetary Price: 2.07959 USD; CLASS: IO; Country of Origin: China, Costa Rica, Malaysia, Singapore, Taiwan, United States, Vietnam; Datasheet URL: https://suddendocs.samtec.com/catalog_english/ftsh_smt.pdf; Datasheet URL 1: http://www.samtec.com/documents/webfiles/cpdf/FTSH-1XX-XX-XXX-DV-XXX-MKT.pdf; Datasheet URL 2: http://www.samtec.com/documents/webfiles/pdf/FTSH_SMT.PDF; FPLIST: SAMTEC_FTSH-105-01-F-DV-K-10N,SAMTEC_FTSH-105-01-F-DV-K-10L,SAMTEC_FTSH-105-01-F-DV-K-10M; Lead Time: 14; LifeCycle Status: MATURITY; MPN Status: ACTIVE; Manufacturer: SAMTEC; Mass: 0.31700g; Max Oper Temp: +125DEGC; Maximum Operating Temperature: +125DEGC; Min Oper Temp: -55DEGC; Minimum Operating Temperature: -55DEGC; Mounting Type: SMD; NOTE Status: PREFERRED; NOTEfied URL: https://dev-webinterface.dpserver.no/item/7308603; No Of Pos: 10; No Of Rows: 2; Number of Positions: 10; Number of Rows: 2; Old Footprint: SAMTEC_FTSH-105-01-F-DV-K-10N,CONN_MALE_2X5; Packing Size: 92; Packing Type: Tube; Part Number: 06-00166; Part Type: Connector|HEADER|STANDARD; Pitch: 1.27mm; REACH/SVHC Compliance: Compliant; REACH/SVHC Details: SVHC List Version Jun 20, 2016; REACH/SVHC Source: Material Declaration; REACH/SVHC Status: Unaffected; ROHS: Compliant; Rated Current: 3.4A; Revision: R034; RoHS Status: ROHS_COMPLIANT; Rtd Current: 1.75A; Status: Released; Texas Part Status: Under Review; Type: Connector; Vendor: SAMTEC; Vendor Part Status: Active; WEIGHT: 0.65614g
U4 = IC_EEPROM_CAT24C08_TSOT23-5: IC, MEMORY, EEPROM, SERIAL, I2C, 8kbit, 1k X 8bit, 900ns, 1.7V TO 5.5V, TSOT23-5, SMD; ALT_SYMBOLS: SOT95P280X100-5A2L,SOT95P280X100-5A2M; Additional Datasheet URL: https://www.onsemi.com/products/timing-logic-memory/memory/eeprom-memory/cat24c08; Budgetary Price: .1867 USD; Country of Origin: Thailand; Datasheet URL: https://www.onsemi.com/download/data-sheet/pdf/cat24c01-d.pdf; Lead Time: 23; Mass: 0.01268g; Maximum Operating Temperature: +85DEGC; Minimum Operating Temperature: -40DEGC; Mounting Type: SMD; NOTEfied URL: https://dev-webinterface.dpserver.no/item/25158614; PCB Package: TSOT23-5; Packing Size: 3000; Packing Type: Tape & Reel; Part Number: 18-36044; Part Type: IC|EEPROM|SERIAL|I2C; REACH/SVHC Compliance: Compliant; REACH/SVHC Details: SVHC List Version Jan 16, 2020; REACH/SVHC Source: REACH Declaration; REACH/SVHC Status: Unaffected; ROHS: Compliant; Rated Voltage: 1.7V TO 5.5V; Revision: R007; Status: Released; Texas Part Status: Under Review; Type: IC; Vendor: ONSEMI; Vendor Part Number: CAT24C08TDI-GT3; Vendor Part Status: Active
FIDU1-FIDU6 = FIDMARK: NON COMPONENT, FIDUCIAL MARK, ROUND 1.27MM, SMD; Additional Datasheet URL: N/A; CLASS: IO; Country of Origin: Missing Info; Datasheet URL: N/A; Mass: N/A; Mounting Type: SMD; NOTEfied URL: https://dev-webinterface.dpserver.no/item/7504224; Packing Size: N/A; Packing Type: Missing Info; Part Number: 19-00300; Part Type: Non Component|FIDUCIAL; ROHS: Not Applicable; Revision: R020; Status: Released; Texas Part Status: Under Review; Type: Non Component; Vendor: NON_COMPONENT; Vendor Part Number: FIDUCIAL_1.27mm; Vendor Part Status: Active
LBL1 = TI_LOGO_V1: NON COMPONENT, LABEL, TEXAS INSTRUMENTS LOGO; Additional Datasheet URL: N/A; AutoDoc File: https://notefied-dynamic-precision.com/DB/Apps/Desktop/Item/Object.aspx?id=87770; BU Name: TEXAS INSTRUMENTS NORWAY; Country of Origin: Missing Info; Datasheet URL: N/A; Mass: N/A; Mounting Type: NOT APPLY; NOTEfied URL: https://dev-webinterface.dpserver.no/item/7504541; Notes: Custom Item; Packing Size: N/A; Packing Type: Missing Info; Part Number: 19-00350; Part Type: Non Component|LABEL; ROHS: Not Applicable; Revision: R023; Status: Released; Texas Part Status: Under Review; Type: Non Component; Vendor: NON_COMPONENT; Vendor Part Status: Active
LBL2 = TRASH_V2: NON COMPONENT, LABEL, TRASH 7mm; Additional Datasheet URL: N/A; Country of Origin: Missing Info; Datasheet URL: N/A; Mass: N/A; Mounting Type: NOT APPLY; NOTEfied URL: https://dev-webinterface.dpserver.no/item/14983721; Packing Size: N/A; Packing Type: Missing Info; Part Number: 19-01044; Part Type: Non Component|LABEL; ROHS: Not Applicable; Revision: R016; Status: Released; Texas Part Status: Under Review; Type: Non Component; Vendor: NON_COMPONENT; Vendor Part Status: Active
LBL3 = ESD_LABEL: NON COMPONENT, LABEL, ESD, 5 X 5 mm; Additional Datasheet URL: N/A; Country of Origin: Missing Info; Datasheet URL: N/A; Mass: N/A; Maximum Operating Temperature: N/A; Minimum Operating Temperature: N/A; Mounting Type: NOT APPLY; NOTEfied URL: https://dev-webinterface.dpserver.no/item/7504774; Packing Size: N/A; Packing Type: Missing Info; Part Number: 19-00471; Part Type: Non Component|LABEL; ROHS: Not Applicable; Revision: R009; Status: Released; Type: Non Component; Vendor: NON_COMPONENT; Vendor Part Status: Active
LBL5 = LABEL_FOR_EVALUATOIN_ONLY: NON COMPONENT, LABEL, FOR EVALUATION ONLY, NOT FCC APPROVED FOR RESALE; Additional Datasheet URL: N/A; AutoDoc File: https://notefied-dynamic-precision.com/DB/Apps/Desktop/Item/Object.aspx?id=115268; BU Name: TEXAS INSTRUMENTS NORWAY; Country of Origin: Missing Info; Datasheet URL: N/A; Mass: N/A; Maximum Operating Temperature: N/A; Minimum Operating Temperature: N/A; Mounting Type: NOT APPLY; NOTEfied URL: https://dev-webinterface.dpserver.no/item/7505603; Notes: Custom Item; Packing Size: N/A; Packing Type: Missing Info; Part Number: 19-00830; Part Type: Non Component|LABEL; REACH/SVHC Compliance: Missing Info; REACH/SVHC Details: N/A; REACH/SVHC Source: N/A; REACH/SVHC Status: Missing Info; ROHS: Not Applicable; Revision: R023; Status: Released; Texas Part Status: Under Review; Type: Non Component; Vendor: NON_COMPONENT; Vendor Part Status: Active
M1 M2 M7 M8 = MECH_SHUNT_JUMPER_V1: MECHANIC, SHUNT, CURRENT RATING 4.3A PER PIN, 2.54 X 5.08 X 6.1mm, BLACK; Additional Datasheet URL: https://www.samtec.com/products/snt-100-bk-g; AutoDoc File: https://notefied-dynamic-precision.com/DB/Apps/Desktop/Item/Object.aspx?id=104092; BU Name: DYNAMIC PRECISION GDANSK; Budget Currency: USD; Budget Price: 0.146; Budgetary Price: .19442 USD; Client Status: UNDER_REVIEW; Country of Origin: China, Costa Rica, Malaysia, Singapore, Taiwan, United States, Vietnam; Datasheet URL: https://suddendocs.samtec.com/catalog_english/snt.pdf; Datasheet URL 1: http://suddendocs.samtec.com/catalog_english/snt.pdf; Datasheet URL 2: http://suddendocs.samtec.com/prints/snt-100-xx-x-x-mkt.pdf; Lead Time: 9; Mass: 0.52432g; Max Oper Temp: +125DEGC; Maximum Operating Temperature: +125DEGC; Min Oper Temp: -55DEGC; Minimum Operating Temperature: -55DEGC; Mounting Type: NOT APPLY; NOTEfied URL: https://dev-webinterface.dpserver.no/item/7503385; Packing Size: 1; Packing Type: Bulk; Part Number: 19-00498; Part Type: Mechanic|SHUNT; REACH/SVHC Compliance: Compliant; REACH/SVHC Details: SVHC List Version Dec 17, 2015; REACH/SVHC Source: Material Declaration; REACH/SVHC Status: Unaffected; REACH/SVHC_COMPLIANCE: COMPLIANT; REACH/SVHC_DETAILS: SVHC LIST VERSION Dec 17, 2015; REACH/SVHC_SOURCE: MATERIAL DECLARATION; REACH/SVHC_STATUS: UNAFFECTED; ROHS: Compliant; Rated Current: 4.3A; Revision: R028; RoHS Status: ROHS_COMPLIANT; Rtd Current: 4.3A; Status: Released; Texas Part Status: Under Review; Type: Mechanic; Vendor: SAMTEC; Vendor Part Status: Active; Weight: 0.11724g
M3-M6 = MECH_SPACERS_SUPPORT_V1: MECHANIC, ACCESSORY, SPACER SUPPORT, PCB DIA. 3mm, NYLON 66, NPTH; Additional Datasheet URL: https://www.kangyang-europe.com/product/pc-board-hardware/dcb-12d/; Country of Origin: Missing Info; Datasheet URL: https://www.kangyang-europe.com/wp-content/uploads/2020/02/DCB-HD.pdf; Maximum Operating Temperature: N/A; Minimum Operating Temperature: N/A; Mounting Type: NPTH; NOTEfied URL: https://dev-webinterface.dpserver.no/item/44342418; Notes: Custom libraries; Packing Size: 1000; Packing Type: Missing Info; Part Number: 13-07898; Part Type: Mechanic|ACCESSORY; REACH/SVHC Compliance: Compliant; REACH/SVHC Details: SVHC List Version Jul 7, 2017; REACH/SVHC Source: REACH Declaration; REACH/SVHC Status: Unaffected; ROHS: Compliant; Revision: R018; Status: Released; Texas Part Status: Under Review; Type: Mechanic; Vendor: SUZHOU SOLY ELECTRICIAN; Vendor Part Status: Active
MH1-MH4 = HOLE_PTH: NON COMPONENT, HOLE 3.2mm, PLATED, PAD SIZE 3.8mm; Additional Datasheet URL: N/A; Country of Origin: Missing Info; Datasheet URL: N/A; Mass: N/A; Mounting Type: NOT APPLY; NOTEfied URL: https://dev-webinterface.dpserver.no/item/7503683; Packing Size: N/A; Packing Type: Missing Info; Part Number: 19-00083; Part Type: Non Component|HOLE|PLATED; ROHS: Not Applicable; Revision: R022; Status: Released; Type: Non Component; Vendor: NON_COMPONENT; Vendor Part Status: Active
MH5 = HOLE_PTH: NON COMPONENT, HOLE 1.1mm, PLATED, PAD SIZE 1.7mm; Additional Datasheet URL: N/A; Country of Origin: Missing Info; Datasheet URL: N/A; Mass: N/A; Mounting Type: NOT APPLY; NOTEfied URL: https://dev-webinterface.dpserver.no/item/7503643; Packing Size: N/A; Packing Type: Missing Info; Part Number: 19-00062; Part Type: Non Component|HOLE|PLATED; ROHS: Not Applicable; Revision: R007; Status: Released; Type: Non Component; Vendor: NON_COMPONENT; Vendor Part Number: HOLE_1.1mm_PLATED; Vendor Part Status: Active

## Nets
5V0_BP: J1.2 P3.3 P5.1 U4.4(VCC)
GND: C55.2 CR1.1(C) CR2.1(C) CR8.4(GND) J1.4 J2.2 MH3.1 MH4.1 MH5.1 P1.2 P1.3 P3.1 P3.2 P3.8 P3.14 P3.20 P4.3 P4.5 P4.9 P5.2 P5.3 SW1.1 SW1.2 SW1.3 SW2.1 SW2.2 SW2.4 U3.4(GND) U3.9(EGP) U4.2(VSS) U4.5(WP) ; also on sheet 1
BP_RESET: J2.11 R52.1
BTN1: J2.16 P6.6 R56.2
BTN2: J2.18 P6.1 R55.2
DIO3: J1.15 ; also on sheet 1
DIO4: J1.9 ; also on sheet 1
DIO8_SDA: P2.5 R69.2
DIO8_SDA_T: R69.1 U1.C2(DIO8)
DIO11: R19.1 R20.1 U1.B1(DIO11)
DIO11_CS: J2.6 R19.2
DIO11_FLASH_CS: J2.5 R20.2 R24.1 U3.1(nCS)
DIO12_PICO: J2.12 U1.B2(DIO12) U3.5(SI/SIO0)
DIO18_SCLK: P6.5 U1.B3(DIO18)
DIO21_A10_POCI: P2.2 U1.A4(DIO21_A10)
DIO24_A7_SCL: P6.2 R68.1
DIO24_A7_SCL_T: R68.2 U1.C4(DIO24_A7)
GLED: J2.1 P2.6 R15.2
LP_RESET: J2.10 R51.1
POCI: J2.14 P2.4 U3.2(SO/SIO1)
RLED: J2.3 P2.1 R14.2
SCL: J1.17 P6.4 R67.1
SCLK: J1.13 P6.3 U3.6(SCLK)
SDA: J1.19 P2.3 R66.1
WMCU_RESET: CR8.3(IO3) P3.11 P4.10 R51.2 R52.2 ; also on sheet 1
WMCU_RXD: J1.5 P3.7 U1.A3(DIO20_A11)
WMCU_SWDCK: CR8.6(IO5) P3.15 P4.4 R5.2 ; also on sheet 1
WMCU_SWDIO: CR8.7(IO6) P3.13 P4.2 R4.2 ; also on sheet 1
WMCU_TXD: J1.7 P3.9 U1.D3(DIO6_A1)
WMCU_VDD: CR8.8(VCC) J1.1 P1.1 P3.5 P4.1 R22.1 R23.1 R24.2 R25.2 R66.2 R67.2 ; also on sheet 1
XDS_BoardID_SCL: P3.6 U4.1(SCL)
XDS_BoardID_SDA: P3.4 U4.3(SDA)
N3109894: J2.13 R4.1
N3109960: J2.15 R5.1
N3110768: R56.1 SW1.4
N3110772: R55.1 SW2.3
N3110876: CR1.2(A) R15.1
N3110880: CR2.2(A) R14.1
N3111246: C55.1 R25.1 U3.8(VCC)
N3111262: R22.2 U3.7(nRST/SIO3)
N3111266: R23.2 U3.3(nWP/SIO2)

Not connected (* = marked no-connect by the designer): CR8 1(IO1)* 2(IO2)* 5(IO4)*; FIDU1 1*; FIDU2 1*; FIDU3 1*; FIDU4 1*; FIDU5 1*; FIDU6 1*; J1 3* 6* 8* 10* 11* 12* 14* 16* 18* 20*; J2 4* 7* 8* 9* 17* 19* 20*; MH1 1*; MH2 1*; P3 10* 12* 16* 17* 18* 19*; P4 6* 7* 8*

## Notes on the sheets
sheet 2
- BoosterPack Headers and Peripherals
- 40
- 20
- 1
- 2
- 21
- 22
- 38
- 39
- 18
- 19
- 5V and 3V headers
- 3
- 23
- 37
- 17
- 4
- 24
- 36
- 16
- 5
- 25
- 35
- 15
- 6
- 26
- 34
- 14
- 7
- 8
- 27
- 28
- 32
- 33
- 12
- 13
- 9
- 29
- 31
- 11
- 10
- 30
- Wireless MCU IO block
- External flash
- Buttons / LEDs
- If external flash mounted, default to FLASH_CS
- SPI 2-4, RLED 2-1
  I2C 5-3, GLED 5-6
- I2C 2-4, BTN2 2-1
  SPI 5-3, BTN1 5-6
sheet 3
- XDS110 Debugger Interface
- Board ID
- DEBUG
- Use P4 for debugging
  the wireless MCU with an
  external debugger
sheet 4
- Mechanical
- Labels
- Jumpers P2 and P6
- Fiducials
- Mounting Holes
